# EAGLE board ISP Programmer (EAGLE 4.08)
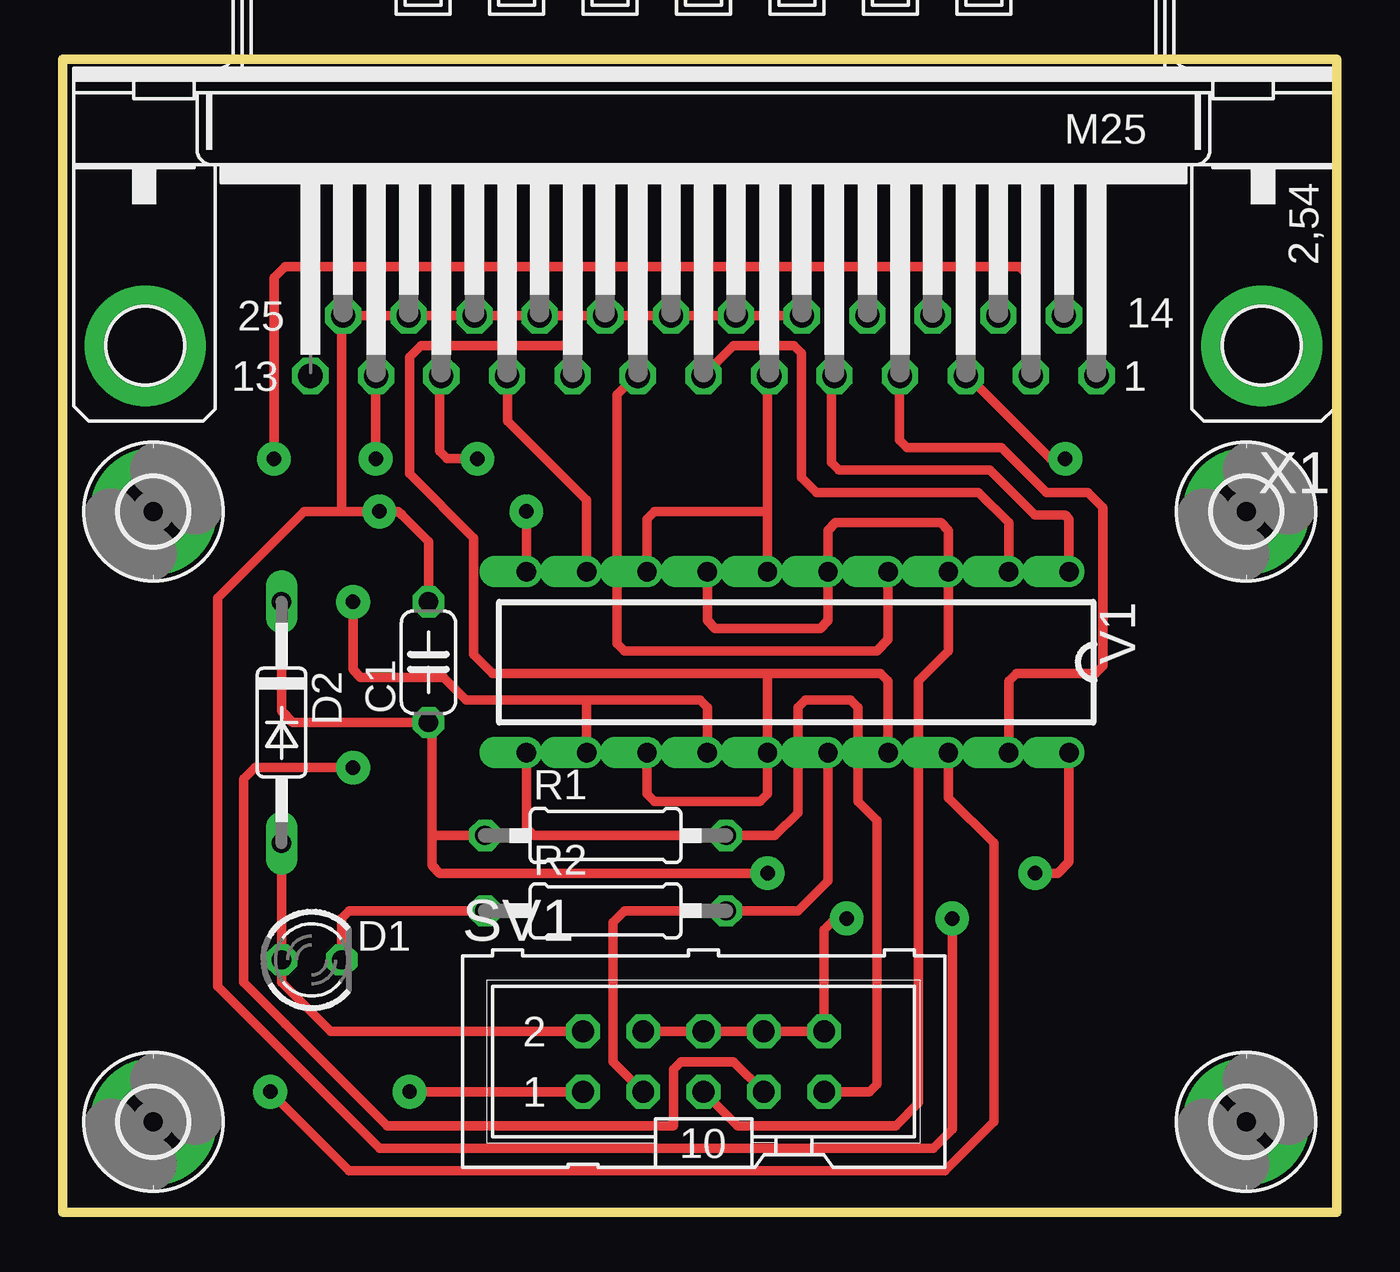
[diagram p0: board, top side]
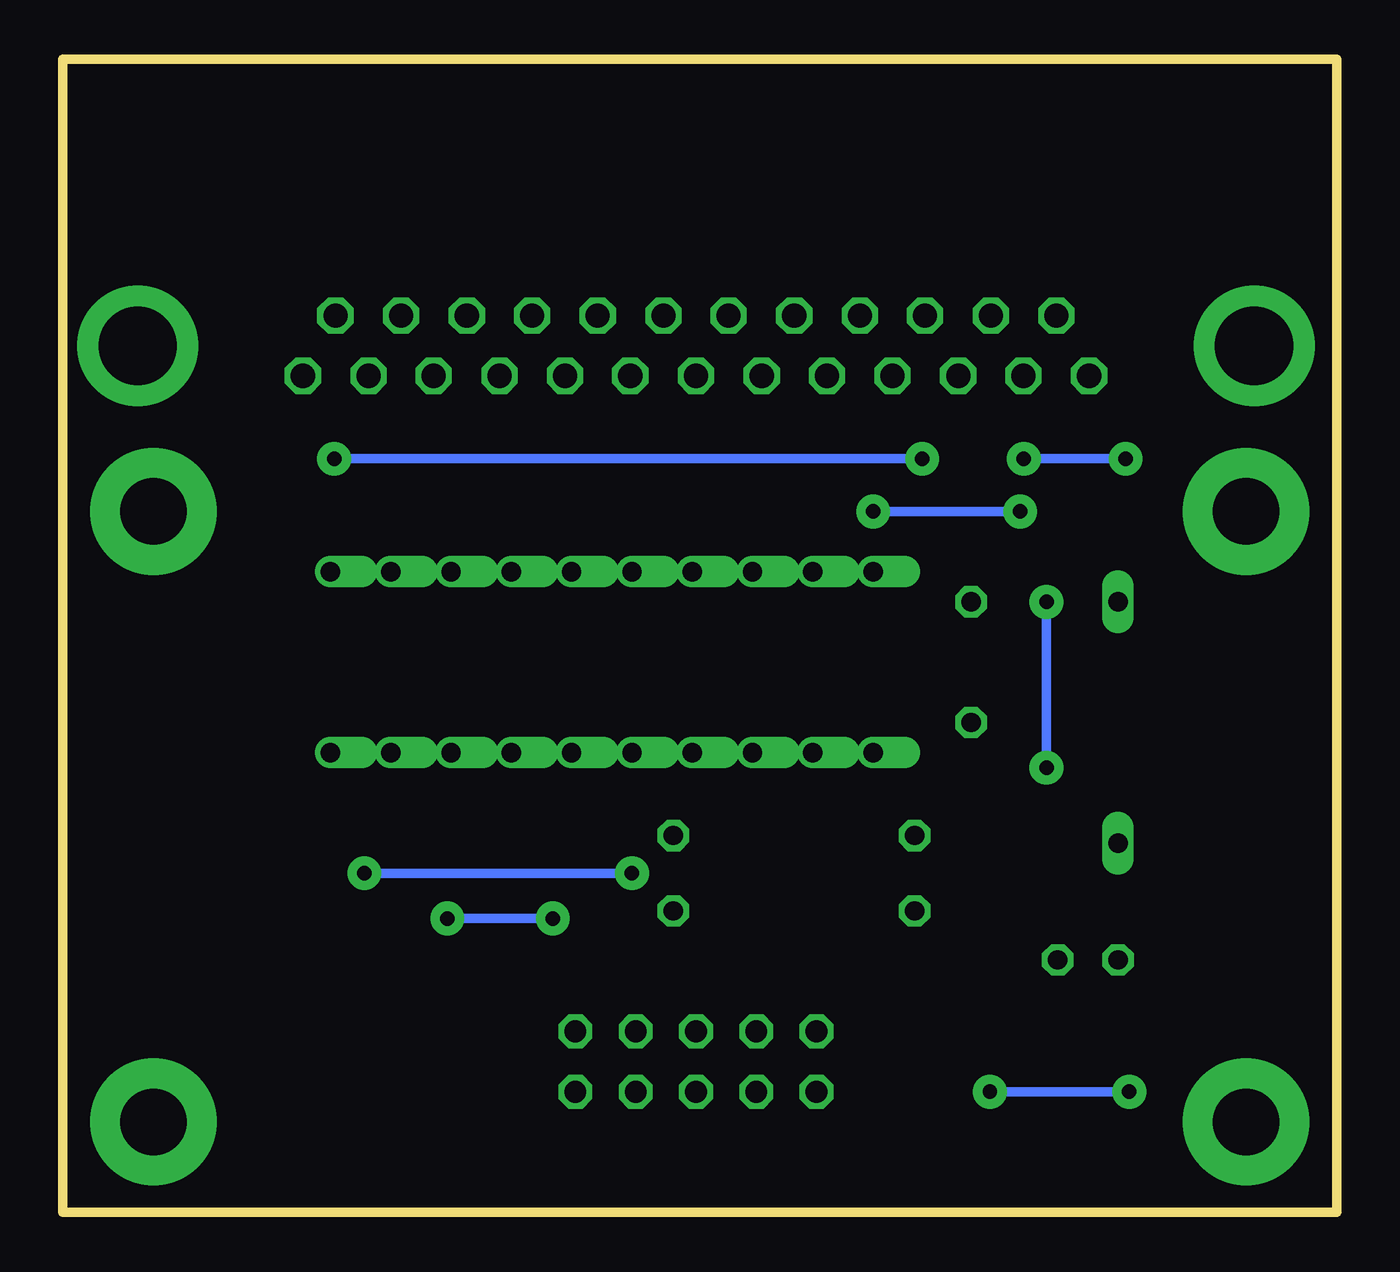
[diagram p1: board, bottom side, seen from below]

Size 53.96 x 48.58 mm. Coordinates in mm from the lower left corner, seen from the top.
Outline: 0,0.01 53.96,0.01
Outline: 53.96,48.57 0,48.57
Outline: 0.15,0 53.81,0 53.81,48.58 0.15,48.58 0.15,0
Copper layers used: Top, Bottom

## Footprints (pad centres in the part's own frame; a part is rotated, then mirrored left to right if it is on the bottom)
C050-024X044 = drill 0.813 octagon: 1 -2.54,0; 2 2.54,0
LED3MM = drill 0.813 octagon: A -1.27,0; K 1.27,0
DO35-10 = drill 0.813 long: A 5.08,0; C -5.08,0
2,8-PAD = drill 2.8 pad 5.334 round: B2,8 0,0
0207/10 = drill 0.813 octagon: 1 -5.08,0; 2 5.08,0
ML10 = drill 0.914 octagon: 1 -5.08,-1.27; 2 -5.08,1.27; 3 -2.54,-1.27; 4 -2.54,1.27; 5 0,-1.27; 6 0,1.27; 7 2.54,-1.27; 8 2.54,1.27; 9 5.08,-1.27; 10 5.08,1.27
DIL20 = drill 0.813 offset: 1 -11.43,-3.81; 2 -8.89,-3.81; 3 -6.35,-3.81; 4 -3.81,-3.81; 5 -1.27,-3.81; 6 1.27,-3.81; 7 3.81,-3.81; 8 6.35,-3.81; 9 8.89,-3.81; 10 11.43,-3.81; 11 11.43,3.81; 12 8.89,3.81; 13 6.35,3.81; 14 3.81,3.81; 15 1.27,3.81; 16 -1.27,3.81; 17 -3.81,3.81; 18 -6.35,3.81; 19 -8.89,3.81; 20 -11.43,3.81
M25HP = drill 1.016 octagon: 1 -16.561,1.27; 2 -13.792,1.27; 3 -11.049,1.27; 4 -8.28,1.27; 5 -5.512,1.27; 6 -2.769,1.27; 7 0,1.27; 8 2.769,1.27; 9 5.512,1.27; 10 8.28,1.27; 11 11.049,1.27; 12 13.792,1.27; 13 16.561,1.27; 14 -15.189,-1.27; 15 -12.421,-1.27; 16 -9.652,-1.27; 17 -6.909,-1.27; 18 -4.14,-1.27; 19 -1.372,-1.27; 20 1.372,-1.27; 21 4.14,-1.27; 22 6.909,-1.27; 23 9.652,-1.27; 24 12.421,-1.27; 25 15.189,-1.27 | drill 3.302 pad 5.08 round: G1 -23.52,0; G2 23.52,0

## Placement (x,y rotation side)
C1  [C050-024X044]  15.55,23.18 90 top
D1  LED3MM  [LED3MM]  10.63,10.64 0 top
D2  1N4148  [DO35-10]  9.36,20.64 270 top
E$1  [2,8-PAD]  3.96,29.53 0 top
E$2  [2,8-PAD]  50,29.53 0 top
E$3  [2,8-PAD]  50,3.81 0 top
E$4  [2,8-PAD]  3.96,3.81 0 top
R1  [0207/10]  23.01,15.88 0 top
R2  [0207/10]  23.01,12.7 0 top
SV1  [ML10]  27.14,6.35 0 top
V1  74244N  [DIL20]  31.11,23.18 180 top
X1  [M25HP]  27.14,36.51 180 top

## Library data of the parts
C1 R1 R2 = rcl
D1 = led
D2 = diode
E$1-E$4 = holes
SV1 = con-harting-ml
V1 = 74ttl-din
X1 = con-subd

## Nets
+UB: C1.1 D2.C R1.1 V1.20
GND: C1.2 SV1.4 SV1.10 V1.10
S$5: SV1.2
S$7: R1.2 SV1.9 V1.11
S$9: V1.9
S$10: SV1.1 V1.18
S$12: V1.8
S$15: V1.13 V1.15 V1.17
S$17: R2.2 SV1.3 V1.16
S$18: D1.K R2.1
S$19: SV1.7 V1.12 V1.14
S$21: V1.4
S$22: V1.19
S$23: V1.1
S$24: V1.2 X1.7
S$25: SV1.5 V1.3 V1.5 V1.7

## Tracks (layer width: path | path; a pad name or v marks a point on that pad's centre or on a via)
+UB  (via drill 0.61 pad 1.42)
  Top 0.406: D2.C 9.36,21.11 9.84,20.64 C1.1 15.39,20.64 15.71,20.32 15.71,15.88 | R1.1 15.71,15.88 | 15.71,15.88 15.71,14.61 16.03,14.29 v29.84,14.29 | v41.11,14.29 42.06,14.29 42.54,14.76 V1.20
  Bottom 0.406: v29.84,14.29 v41.11,14.29
GND  (via drill 0.61 pad 1.42)
  Top 0.406: 31.27,37.78 11.9,37.78 11.9,29.53 | C1.2 15.55,28.26 14.44,29.37 14.28,29.53 v13.49,29.53 11.9,29.53 | v19.68,29.53 V1.10 | SV1.4 SV1.10 32.22,11.91 32.7,12.38 v33.17,12.38 | v37.62,12.38 37.62,3.49 36.82,2.7 13.49,2.7 6.66,9.53 6.66,25.88 10.31,29.53 11.9,29.53
  Bottom 0.406: v13.49,29.53 v19.68,29.53 | v33.17,12.38 v37.62,12.38
S$3
  Top 0.406: 21.58,35.24 21.58,36.2 21.27,36.51 15.23,36.51 14.76,36.04 14.76,31.11 17.46,28.42 17.46,23.5 18.25,22.7 29.84,22.7
S$4  (via drill 0.61 pad 1.42)
  Top 0.406: 40.95,35.24 40.95,39.37 40.48,39.85 9.52,39.85 9.04,39.37 v9.04,31.75 | v13.33,31.75 13.33,35.24
  Bottom 0.406: v9.04,31.75 v13.33,31.75
S$5
  Top 0.406: SV1.2 11.42,7.62 9.36,9.68 9.36,15.72
S$7
  Top 0.406: V1.11 19.68,16.19 20,15.88 R1.2 30.16,15.88 31.11,16.83 31.11,21.27 31.43,21.59 33.33,21.59 33.65,21.27 33.65,17.3 34.44,16.51 34.44,5.4 34.12,5.08 SV1.9
S$9
  Top 0.406: 18.89,35.24 18.89,33.34 22.22,30 V1.9
S$10  (via drill 0.61 pad 1.42)
  Top 0.406: SV1.1 v14.76,5.08 | v8.88,5.08 12.22,1.75 37.3,1.75 39.36,3.81 39.36,15.56 37.46,17.46 V1.18
  Bottom 0.406: v14.76,5.08 v8.88,5.08
S$11  (via drill 0.61 pad 1.42)
  Top 0.406: 38.25,35.24 41.74,31.75 v42.38,31.75 | v17.62,31.75 16.35,31.75 16.03,32.07 16.03,35.24
  Bottom 0.406: v17.62,31.75 v42.38,31.75
S$12
  Top 0.406: V1.8 24.76,29.21 25.08,29.53 29.84,29.53 | 29.84,35.24 29.84,29.53 | 29.84,29.53 29.84,26.99
S$15
  Top 0.406: V1.17 34.92,22.38 34.6,22.7 29.84,22.7 V1.15 29.84,17.62 29.52,17.3 25.08,17.3 24.76,17.62 V1.13
S$17
  Top 0.406: SV1.3 23.33,6.35 23.33,12.22 23.81,12.7 R2.2 31.11,12.7 32.38,13.97 V1.16
S$18
  Top 0.406: D1.K 11.9,12.38 12.22,12.7 R2.1
S$19  (via drill 0.61 pad 1.42)
  Top 0.406: SV1.7 28.41,6.35 26.19,6.35 25.87,6.03 25.87,3.65 13.81,3.65 9.52,7.94 | 9.52,7.94 | 9.52,7.94 7.77,9.68 7.77,18.26 8.25,18.73 v12.38,18.73 | v12.38,25.72 12.38,22.86 12.69,22.54 16.19,22.54 17.14,21.59 22.22,21.59 | V1.14 27.3,21.27 26.98,21.59 22.22,21.59 | 22.22,21.59 V1.12
  Bottom 0.406: v12.38,25.72 v12.38,18.73
S$21
  Top 0.406: V1.4 34.92,24.13 34.44,23.65 23.81,23.65 23.49,23.97 23.49,34.45 24.28,35.24
S$22
  Top 0.406: V1.19 40,22.38 40.32,22.7 43.65,22.7 43.97,23.02 43.97,29.69 43.33,30.32 41.59,30.32 39.68,32.23 35.71,32.23 35.4,32.54 35.4,35.24
S$23
  Top 0.406: 32.54,35.24 32.54,31.59 32.86,31.27 39.2,31.27 41.11,29.37 42.38,29.37 42.54,29.21 V1.1
S$24
  Top 0.406: V1.2 40,29.05 38.73,30.32 31.9,30.32 31.27,30.96 31.27,36.2 30.95,36.51 28.41,36.51 X1.7
S$25
  Top 0.406: SV1.5 | SV1.5 28.57,3.65 35.24,3.65 36.19,4.6 36.19,22.38 37.46,23.65 V1.3 37.46,28.73 37.14,29.05 32.7,29.05 32.38,28.73 V1.5 32.38,24.92 32.06,24.61 27.62,24.61 27.3,24.92 V1.7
